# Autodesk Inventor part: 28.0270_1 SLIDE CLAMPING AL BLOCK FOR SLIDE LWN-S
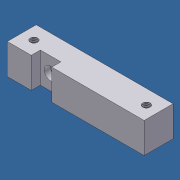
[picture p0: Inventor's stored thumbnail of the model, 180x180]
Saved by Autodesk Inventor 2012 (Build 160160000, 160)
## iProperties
Created: 2007-06
Part Number: 28.0270_1 SLIDE CLAMPING AL BLOCK FOR SLIDE LWN-S
Material: Aluminum-6061
Document SubType Name: Modeling
Designer: Andy Moles
Density: 2.71 g/cm^3
Mass: 84.809 g
Surface Area: 86.2417 cm^2
Volume: 31.2948 cm^3
Author: Andy Moles
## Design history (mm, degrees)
sketch "Sketch1"
  geometry: L1 (-29.25, -3.5)-(-29.25, -9.5); L2 (-29.25, -9.5)-(-45, -9.5); L3 (-45, -9.5)-(-45, 9.5); L4 (-45, 9.5)-(45, 9.5); L5 (45, 9.5)-(45, -9.5); L6 (45, -9.5)-(-15.75, -9.5); L7 (-15.75, -9.5)-(-15.75, -3.5); L8 (-45, 0)-(-49.68, 0); L9 (-29.25, -3.5)-(-15.75, -3.5); L10 (-22.5, -3.5)-(-22.5, 2.838); 3 further points
  constraints: 20 end point, 4 parallel, 3 horizontal, 3 midpoint, 2 horizontal alignment, 2 perpendicular, 1 vertical, 1 vertical alignment
  dimensions: "d0" = 19 distance of L2.end L3.end; "d1" = 90 distance of L3.end L4.end; "d2" = 6 distance of L6.end L7.end; "d3" = 13.5 distance of L7.end L1.start; "d5" = 0 distance from line of L8 point (0, 0); "d26" = 22.5 distance from line of point (0, 0) L10
extrude "Extrusion1" new body sketch "Sketch1" distance "d8" = 20; taper "d9" = 0 deg
sketch "Sketch2"
  geometry: 3 further points
  constraints: 2 horizontal alignment
  dimensions: "d27" = 74 distance of point (37, 0) point (-37, 0); "d28" = 37 distance of point (37, 0) point (0, 0) (= 0.5 x d27)
hole "Hole3" sketch "Sketch2" at (-37, 0), (37, 0) diameter "d29" = 4.917; stored, may be unused: countersink angle "d33" = 90 deg, drill point angle "d35" = 118 deg; dims "d30" = 6, "d31" = 4, "d32" = 2, "d34" = 8
sketch "Sketch3"
  geometry: L1 (0, 0)-(13.5, 0) reference; L2 (0, 0)-(0, -20) reference; C1 r 3.25 at (6.75, -10); 3 further points
  constraints: 2 midpoint, 1 centre point, 1 horizontal alignment, 1 vertical alignment
  dimensions: "d36" = 6.5 diameter of C1
extrude "Extrusion2" cut sketch "Sketch3" stored distance "d37" = 10; taper "d38" = 0 deg
hole "Hole4" diameter "d41" = 8.5; stored, may be unused: countersink angle "d45" = 90 deg, drill point angle "d47" = 0 deg; dims "d39" = 10, "d40" = 10, "d42" = 6, "d43" = 4, "d44" = 2, "d46" = 4
body "Solid1"
